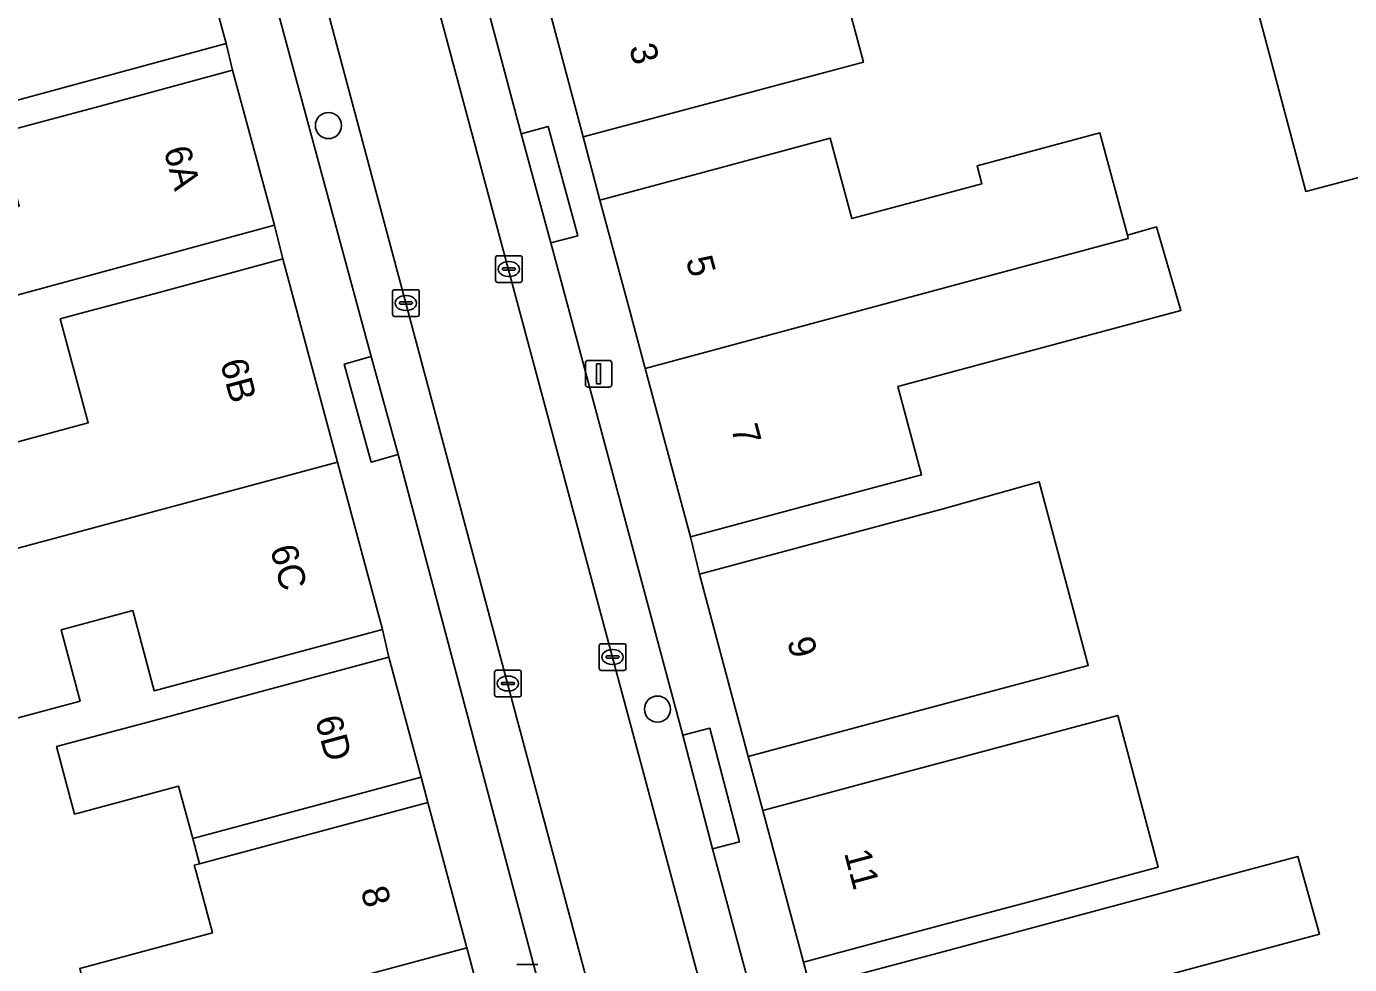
# Model space of a CAD drawing. Extents: x 159262 to 160143, y 383399 to 384319.
# Drawn here: x 159630.85 to 159680.37, y 383725.57 to 383760.7 of the extents above; entities that cross this region are included whole.
import ezdxf

# ---------------------------------------------------------------- set-up
doc = ezdxf.new("R2010")
doc.units = 0
for name, color, linetype in [('IMGEO_Boom', 7, 'Continuous'), ('IMGEO_Erf', 7, 'Continuous'), ('IMGEO_Kolk', 7, 'Continuous'), ('IMGEO_Lichtmast', 7, 'Continuous'), ('IMGEO_Pand', 7, 'Continuous'), ('IMGEO_Pand_nummerreeks', 7, 'Continuous'), ('IMGEO_Pand_overbouw', 7, 'Continuous'), ('IMGEO_Parkeervlak_open', 7, 'Continuous'), ('IMGEO_Rijbaan_lokaal_open', 7, 'Continuous'), ('IMGEO_Voetpad_open', 7, 'Continuous')]:
    doc.layers.add(name, color=color, linetype=linetype)

msp = doc.modelspace()

# ---------------------------------------------------------------- linework, layer by layer
at = {"layer": 'IMGEO_Boom'}
for centre in [(159642.151, 383756.987), (159654.468, 383735.137)]:
    msp.add_circle(centre, 0.489, dxfattribs=at)
at = {"layer": 'IMGEO_Erf'}
for points in [[(159683.357, 383755.742), (159678.738, 383754.518), (159676.681, 383762.286)], [(159661.505, 383761.882), (159662.178, 383759.355), (159659.929, 383758.756), (159656.516, 383757.847), (159651.684, 383756.561), (159652.309, 383754.199), (159657.139, 383755.493), (159660.936, 383756.51), (159661.74, 383753.506), (159666.613, 383754.811), (159666.436, 383755.473), (159671.031, 383756.711), (159672.062, 383752.88), (159673.142, 383753.193), (159674.06, 383750.058), (159668.29, 383748.512), (159663.466, 383747.219), (159664.354, 383743.907), (159660.535, 383742.884), (159655.705, 383741.589), (159656.036, 383740.193), (159660.866, 383741.487), (159665.168, 383742.639), (159668.752, 383743.653), (159669.679, 383740.196), (159670.596, 383736.774), (159667.032, 383735.819), (159662.696, 383734.657), (159657.866, 383733.363), (159658.411, 383731.343), (159663.241, 383732.637), (159671.696, 383734.902), (159673.216, 383729.215), (159668.485, 383727.949), (159664.763, 383726.955), (159659.933, 383725.661), (159660.182, 383724.724), (159665.012, 383726.018), (159676.677, 383729.15), (159678.437, 383729.623), (159679.256, 383726.709), (159677.496, 383726.237), (159673.262, 383725.102)], [(159630.155, 383756.787), (159633.739, 383757.756), (159638.565, 383759.062), (159638.317, 383760.056), (159633.491, 383758.75), (159629.907, 383757.78)], [(159630.39, 383745.113), (159633.161, 383745.858), (159632.114, 383749.754), (159633.035, 383750), (159635.621, 383750.691), (159640.446, 383751.999), (159640.137, 383753.253), (159635.311, 383751.947), (159631.406, 383750.89), (159628.728, 383750.164)], [(159632.841, 383725.424), (159635.39, 383726.109), (159637.808, 383726.759), (159637.21, 383728.99), (159637.128, 383729.296), (159637.322, 383729.348), (159641.037, 383730.346), (159645.865, 383731.643), (159645.621, 383732.59), (159640.793, 383731.293), (159637.068, 383730.292), (159636.541, 383732.254), (159632.65, 383731.209), (159631.971, 383733.734), (159635.861, 383734.779), (159639.588, 383735.78), (159644.416, 383737.077), (159644.171, 383738.119), (159639.343, 383736.822), (159635.63, 383735.824), (159634.823, 383738.829), (159632.14, 383738.109), (159632.856, 383735.441), (159627.833, 383734.093)]]:
    msp.add_lwpolyline(points, dxfattribs=at)
at = {"layer": 'IMGEO_Kolk'}
for p, q in [((159648.404, 383751.188), (159648.404, 383752.04)), ((159648.479, 383752.114), (159649.331, 383752.114)), ((159648.892, 383751.894), (159648.917, 383751.894)), ((159649.405, 383752.04), (159649.405, 383751.188)), ((159648.663, 383751.608), (159648.663, 383751.62)), ((159649.101, 383751.571), (159648.703, 383751.571)), ((159648.706, 383751.657), (159649.104, 383751.657)), ((159648.915, 383751.334), (159648.89, 383751.334)), ((159649.147, 383751.62), (159649.147, 383751.608)), ((159644.625, 383750.84), (159645.477, 383750.84)), ((159649.331, 383751.114), (159648.479, 383751.114)), ((159644.55, 383749.914), (159644.55, 383750.766)), ((159644.809, 383750.334), (159644.809, 383750.346)), ((159644.852, 383750.383), (159645.25, 383750.383)), ((159645.038, 383750.62), (159645.063, 383750.62)), ((159645.293, 383750.346), (159645.293, 383750.334)), ((159645.551, 383750.766), (159645.551, 383749.914)), ((159645.477, 383749.84), (159644.625, 383749.84)), ((159645.247, 383750.297), (159644.849, 383750.297)), ((159645.061, 383750.06), (159645.036, 383750.06)), ((159652.286, 383736.66), (159652.286, 383737.512)), ((159652.361, 383737.586), (159653.213, 383737.586)), ((159653.287, 383737.512), (159653.287, 383736.66)), ((159652.545, 383737.08), (159652.545, 383737.092)), ((159652.983, 383737.043), (159652.585, 383737.043)), ((159652.588, 383737.129), (159652.986, 383737.129)), ((159652.774, 383737.366), (159652.799, 383737.366)), ((159653.029, 383737.092), (159653.029, 383737.08)), ((159648.368, 383735.67), (159648.368, 383736.522)), ((159648.443, 383736.596), (159649.295, 383736.596)), ((159649.369, 383736.522), (159649.369, 383735.67)), ((159653.213, 383736.586), (159652.361, 383736.586)), ((159652.797, 383736.806), (159652.772, 383736.806)), ((159648.627, 383736.09), (159648.627, 383736.102)), ((159649.065, 383736.053), (159648.667, 383736.053)), ((159648.67, 383736.139), (159649.068, 383736.139)), ((159648.856, 383736.376), (159648.881, 383736.376)), ((159649.111, 383736.102), (159649.111, 383736.09)), ((159649.295, 383735.596), (159648.443, 383735.596)), ((159648.879, 383735.816), (159648.854, 383735.816))]:
    msp.add_line(p, q, dxfattribs=at)
for points in [[(159648.404, 383751.188), (159648.404, 383752.04)], [(159648.479, 383752.114), (159649.331, 383752.114)], [(159649.405, 383752.04), (159649.405, 383751.188)], [(159644.625, 383750.84), (159645.477, 383750.84)], [(159649.331, 383751.114), (159648.479, 383751.114)], [(159644.55, 383749.914), (159644.55, 383750.766)], [(159645.551, 383750.766), (159645.551, 383749.914)], [(159645.477, 383749.84), (159644.625, 383749.84)], [(159652.286, 383736.66), (159652.286, 383737.512)], [(159652.361, 383737.586), (159653.213, 383737.586)], [(159653.287, 383737.512), (159653.287, 383736.66)], [(159648.368, 383735.67), (159648.368, 383736.522)], [(159648.443, 383736.596), (159649.295, 383736.596)], [(159649.369, 383736.522), (159649.369, 383735.67)], [(159653.213, 383736.586), (159652.361, 383736.586)], [(159649.295, 383735.596), (159648.443, 383735.596)]]:
    msp.add_lwpolyline(points, dxfattribs=at)
for centre, radius, start, end in [((159648.481, 383752.038), 0.0765, 91.552, 178.448), ((159648.481, 383752.038), 0.0765, 91.552, 178.448), ((159649.329, 383752.038), 0.0765, 1.552, 88.448), ((159649.329, 383752.038), 0.0765, 1.552, 88.448), ((159648.703, 383751.617), 0.0403, 85.8775, 175.7526), ((159648.7, 383751.607), 0.0366, 178.938, 274.7102), ((159649.104, 383751.614), 0.043, 264.8664, 352.4533), ((159649.108, 383751.619), 0.0386, 1.7309, 96.639), ((159644.627, 383750.764), 0.0765, 91.552, 178.448), ((159644.627, 383750.764), 0.0765, 91.552, 178.448), ((159645.475, 383750.764), 0.0765, 1.552, 88.448), ((159645.475, 383750.764), 0.0765, 1.552, 88.448), ((159648.481, 383751.19), 0.0765, 181.552, 268.448), ((159648.481, 383751.19), 0.0765, 181.552, 268.448), ((159649.329, 383751.19), 0.0765, 271.552, 358.448), ((159649.329, 383751.19), 0.0765, 271.552, 358.448), ((159644.849, 383750.343), 0.0403, 85.8775, 175.7526), ((159644.846, 383750.333), 0.0366, 178.938, 274.7102), ((159645.25, 383750.34), 0.043, 264.8664, 352.4533), ((159645.254, 383750.345), 0.0386, 1.7309, 96.639), ((159644.627, 383749.916), 0.0765, 181.552, 268.448), ((159644.627, 383749.916), 0.0765, 181.552, 268.448), ((159645.475, 383749.916), 0.0765, 271.552, 358.448), ((159645.475, 383749.916), 0.0765, 271.552, 358.448), ((159652.363, 383737.51), 0.0765, 91.552, 178.448), ((159652.363, 383737.51), 0.0765, 91.552, 178.448), ((159653.211, 383737.51), 0.0765, 1.552, 88.448), ((159653.211, 383737.51), 0.0765, 1.552, 88.448), ((159652.585, 383737.089), 0.0403, 85.8775, 175.7526), ((159652.582, 383737.079), 0.0366, 178.938, 274.7102), ((159652.986, 383737.086), 0.043, 264.8664, 352.4533), ((159652.99, 383737.091), 0.0386, 1.7309, 96.639), ((159648.445, 383736.52), 0.0765, 91.552, 178.448), ((159648.445, 383736.52), 0.0765, 91.552, 178.448), ((159649.293, 383736.52), 0.0765, 1.552, 88.448), ((159649.293, 383736.52), 0.0765, 1.552, 88.448), ((159652.363, 383736.662), 0.0765, 181.552, 268.448), ((159652.363, 383736.662), 0.0765, 181.552, 268.448), ((159653.211, 383736.662), 0.0765, 271.552, 358.448), ((159653.211, 383736.662), 0.0765, 271.552, 358.448), ((159648.667, 383736.099), 0.0403, 85.8775, 175.7526), ((159648.664, 383736.089), 0.0366, 178.938, 274.7102), ((159649.068, 383736.096), 0.043, 264.8664, 352.4533), ((159649.072, 383736.101), 0.0386, 1.7309, 96.639), ((159648.445, 383735.672), 0.0765, 181.552, 268.448), ((159648.445, 383735.672), 0.0765, 181.552, 268.448), ((159649.293, 383735.672), 0.0765, 271.552, 358.448), ((159649.293, 383735.672), 0.0765, 271.552, 358.448)]:
    msp.add_arc(centre, radius, start, end, dxfattribs=at)
for centre, major_axis, ratio, start_param, end_param in [((159648.891, 383751.614), (-0.387, 0.002), 0.722429, 4.712389, 7.853982), ((159648.916, 383751.614), (-0.39, 0.002), 0.717154, 1.570796, 4.712389), ((159645.037, 383750.34), (-0.387, 0.002), 0.722429, 4.712389, 7.853982), ((159645.062, 383750.34), (-0.39, 0.002), 0.717154, 1.570796, 4.712389), ((159652.773, 383737.086), (-0.387, 0.002), 0.722429, 4.712389, 7.853982), ((159652.798, 383737.086), (-0.39, 0.002), 0.717154, 1.570796, 4.712389), ((159648.855, 383736.096), (-0.387, 0.002), 0.722429, 4.712389, 7.853982), ((159648.88, 383736.096), (-0.39, 0.002), 0.717154, 1.570796, 4.712389)]:
    msp.add_ellipse(centre, major_axis=major_axis, ratio=ratio, start_param=start_param, end_param=end_param, dxfattribs=at)
at = {"layer": 'IMGEO_Lichtmast'}
for p, q in [((159651.769, 383747.294), (159651.769, 383748.094)), ((159651.769, 383748.094), (159651.769, 383747.294)), ((159651.869, 383748.194), (159652.659, 383748.194)), ((159652.659, 383748.194), (159651.869, 383748.194)), ((159652.759, 383748.094), (159652.759, 383747.294)), ((159652.759, 383747.294), (159652.759, 383748.094)), ((159652.659, 383747.194), (159651.869, 383747.194)), ((159651.869, 383747.194), (159652.659, 383747.194)), ((159649.203, 383725.574), (159649.993, 383725.574)), ((159649.993, 383725.574), (159649.203, 383725.574))]:
    msp.add_line(p, q, dxfattribs=at)
msp.add_lwpolyline([(159652.189, 383748.069), (159652.339, 383748.069), (159652.339, 383747.319), (159652.189, 383747.319), (159652.189, 383748.069)], dxfattribs=at)
for centre, start, end in [((159651.869, 383748.094), 90, 180), ((159651.869, 383748.094), 90, 180), ((159652.659, 383748.094), 0, 90), ((159652.659, 383748.094), 360, 90), ((159651.869, 383747.294), 180, 270), ((159651.869, 383747.294), 180, 270), ((159652.659, 383747.294), 270, 0), ((159652.659, 383747.294), 270, 0)]:
    msp.add_arc(centre, 0.1, start, end, dxfattribs=at)
at = {"layer": 'IMGEO_Pand'}
for points in [[(159636.974, 383765.018), (159632.148, 383763.712), (159628.564, 383762.742), (159629.907, 383757.78), (159633.491, 383758.75), (159638.317, 383760.056)], [(159664.041, 383762.557), (159663.412, 383764.92), (159650.383, 383761.448), (159651.684, 383756.561), (159656.516, 383757.847), (159659.929, 383758.756), (159662.178, 383759.355), (159661.505, 383761.882)], [(159681.21, 383763.512), (159676.681, 383762.286), (159678.738, 383754.518), (159683.357, 383755.742)], [(159638.565, 383759.062), (159633.739, 383757.756), (159630.155, 383756.787), (159629.834, 383756.7), (159630.572, 383753.972), (159627.893, 383753.246), (159626.967, 383752.995), (159627.364, 383751.529), (159627.802, 383749.913), (159628.728, 383750.164), (159631.406, 383750.89), (159635.311, 383751.947), (159640.137, 383753.253)], [(159671.031, 383756.711), (159666.436, 383755.473), (159666.613, 383754.811), (159661.74, 383753.506), (159660.936, 383756.51), (159657.139, 383755.493), (159652.309, 383754.199), (159653.44, 383750), (159654.007, 383747.895), (159661.828, 383750), (159667.488, 383751.524), (159672.093, 383752.764), (159672.062, 383752.88)], [(159663.466, 383747.219), (159668.29, 383748.512), (159674.06, 383750.058), (159673.142, 383753.193), (159672.062, 383752.88), (159672.093, 383752.764), (159667.488, 383751.524), (159661.828, 383750), (159654.007, 383747.895), (159655.705, 383741.589), (159660.535, 383742.884), (159664.354, 383743.907)], [(159640.982, 383750), (159640.446, 383751.999), (159635.621, 383750.691), (159633.035, 383750), (159632.114, 383749.754), (159633.161, 383745.858), (159630.39, 383745.113), (159628.437, 383744.588), (159623.533, 383743.27), (159624.531, 383739.558), (159626.243, 383740.018), (159629.259, 383740.827), (159642.491, 383744.379)], [(159642.491, 383744.379), (159629.259, 383740.827), (159626.243, 383740.018), (159627.833, 383734.093), (159632.856, 383735.441), (159632.14, 383738.109), (159634.823, 383738.829), (159635.63, 383735.824), (159639.343, 383736.822), (159644.171, 383738.119)], [(159665.168, 383742.639), (159660.866, 383741.487), (159656.036, 383740.193), (159657.866, 383733.363), (159662.696, 383734.657), (159667.032, 383735.819), (159670.596, 383736.774), (159669.679, 383740.196), (159668.752, 383743.653)], [(159639.588, 383735.78), (159635.861, 383734.779), (159631.971, 383733.734), (159632.65, 383731.209), (159636.541, 383732.254), (159637.068, 383730.292), (159640.793, 383731.293), (159645.621, 383732.59), (159644.416, 383737.077)], [(159671.696, 383734.902), (159663.241, 383732.637), (159658.411, 383731.343), (159659.933, 383725.661), (159664.763, 383726.955), (159668.485, 383727.949), (159673.216, 383729.215)], [(159645.865, 383731.643), (159641.037, 383730.346), (159637.322, 383729.348), (159637.128, 383729.296), (159637.21, 383728.99), (159637.808, 383726.759), (159635.39, 383726.109), (159632.841, 383725.424), (159633.208, 383724.058), (159632.184, 383723.784), (159632.6, 383722.237), (159633.623, 383722.512), (159647.329, 383726.195)], [(159673.262, 383725.102), (159677.496, 383726.237), (159679.256, 383726.709), (159678.437, 383729.623), (159676.677, 383729.15), (159665.012, 383726.018), (159660.182, 383724.724), (159661.751, 383718.867), (159666.582, 383720.161), (159670.051, 383721.115), (159674.048, 383722.198)], [(159647.329, 383726.195), (159633.623, 383722.512), (159632.6, 383722.237), (159632.879, 383721.2), (159633.902, 383721.475), (159634.272, 383720.098), (159639.297, 383721.448), (159640.079, 383718.537), (159643.932, 383719.573), (159648.76, 383720.87)]]:
    msp.add_lwpolyline(points, close=True, dxfattribs=at)
at = {"layer": 'IMGEO_Pand_overbouw'}
for points in [[(159629.907, 383757.78), (159630.155, 383756.787), (159633.739, 383757.756), (159638.565, 383759.062), (159638.317, 383760.056), (159633.491, 383758.75)], [(159637.068, 383730.292), (159637.322, 383729.348), (159641.037, 383730.346), (159645.865, 383731.643), (159645.621, 383732.59), (159640.793, 383731.293)]]:
    msp.add_lwpolyline(points, close=True, dxfattribs=at)
at = {"layer": 'IMGEO_Parkeervlak_open'}
for points in [[(159658.957, 383698.358), (159656.262, 383708.47), (159655.531, 383711.127), (159639.486, 383771.164), (159639.401, 383770.773), (159639.228, 383770.41), (159638.462, 383769.062)], [(159643.962, 383769.967), (159659.468, 383712.142), (159660.175, 383709.486), (159675.226, 383653.663), (159677.362, 383645.771), (159683.923, 383621.261), (159685.312, 383616.758), (159691.977, 383598.671)], [(159638.359, 383768.29), (159643.296, 383750), (159643.745, 383748.335), (159644.756, 383744.665), (159650.603, 383722.664), (159651.489, 383719.443), (159656.5, 383700.639)], [(159693.06, 383602.465), (159688.816, 383614.013), (159688.233, 383613.793), (159688.041, 383614.333), (159686.892, 383617.599), (159685.869, 383620.959), (159685.195, 383623.453), (159683.304, 383630.406), (159681.505, 383637.111), (159680.482, 383640.885), (159670.837, 383676.812), (159669.809, 383680.581), (159656.528, 383729.905), (159655.419, 383734.157), (159651.173, 383750), (159650.479, 383752.591), (159649.37, 383756.675), (159646.528, 383767.317)]]:
    msp.add_lwpolyline(points, dxfattribs=at)
at = {"layer": 'IMGEO_Rijbaan_lokaal_open'}
msp.add_lwpolyline([(159639.765, 383774.003), (159639.486, 383771.164), (159655.531, 383711.127), (159659.468, 383712.142), (159643.962, 383769.967)], dxfattribs=at)
at = {"layer": 'IMGEO_Voetpad_open'}
for points in [[(159635.289, 383778.169), (159633.517, 383777.856), (159633.827, 383776.573), (159635.253, 383771.302), (159636.68, 383766.03), (159636.974, 383765.018), (159638.317, 383760.056), (159638.565, 383759.062), (159640.137, 383753.253), (159640.446, 383751.999), (159640.982, 383750), (159642.491, 383744.379), (159644.171, 383738.119), (159644.416, 383737.077), (159645.621, 383732.59), (159645.865, 383731.643), (159647.329, 383726.195), (159648.76, 383720.87)], [(159656.5, 383700.639), (159651.489, 383719.443), (159650.486, 383719.167), (159649.6, 383722.388), (159650.603, 383722.664), (159644.756, 383744.665), (159643.753, 383744.389), (159642.742, 383748.059), (159643.745, 383748.335), (159643.296, 383750), (159638.359, 383768.29)], [(159660.182, 383724.724), (159659.933, 383725.661), (159658.411, 383731.343), (159657.866, 383733.363), (159656.036, 383740.193), (159655.705, 383741.589), (159654.007, 383747.895), (159653.44, 383750), (159652.309, 383754.199), (159651.684, 383756.561), (159650.383, 383761.448), (159649.082, 383766.334), (159646.528, 383767.317), (159649.37, 383756.675), (159650.374, 383756.948), (159651.483, 383752.864), (159650.479, 383752.591), (159651.173, 383750), (159655.419, 383734.157), (159656.425, 383734.419), (159657.534, 383730.167), (159656.528, 383729.905), (159669.809, 383680.581)]]:
    msp.add_lwpolyline(points, dxfattribs=at)
for points in [[(159649.37, 383756.675), (159650.479, 383752.591), (159651.483, 383752.864), (159650.374, 383756.948)], [(159643.745, 383748.335), (159642.742, 383748.059), (159643.753, 383744.389), (159644.756, 383744.665)], [(159655.419, 383734.157), (159656.528, 383729.905), (159657.534, 383730.167), (159656.425, 383734.419)]]:
    msp.add_lwpolyline(points, close=True, dxfattribs=at)

# ---------------------------------------------------------------- texts
at = {"layer": 'IMGEO_Pand_nummerreeks'}
for s, rotation, p in [('3', 284.9082, (159653.397, 383759.918)), ('6A', 285.1431, (159635.976, 383756.077)), ('5', 285.0743, (159655.52, 383751.968)), ('6B', 285.0227, (159638.091, 383748.116)), ('7', 285.0743, (159657.218, 383745.663)), ('6C', 285.0227, (159639.961, 383741.151)), ('9', 284.9998, (159659.314, 383737.697)), ('6D', 285.0323, (159641.642, 383734.759)), ('11', 284.9954, (159661.445, 383729.754)), ('8', 285.0399, (159643.351, 383728.36))]:
    msp.add_text(s, height=1, rotation=rotation, dxfattribs=at).set_placement(p)

doc.saveas('drawing.dxf')
